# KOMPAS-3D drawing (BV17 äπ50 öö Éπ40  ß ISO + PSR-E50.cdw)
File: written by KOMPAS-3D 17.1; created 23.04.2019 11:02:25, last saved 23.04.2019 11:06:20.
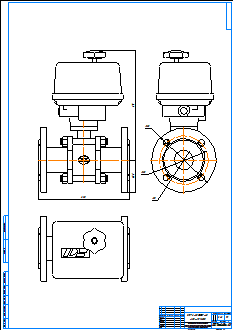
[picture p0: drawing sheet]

Sheet 1: A1, portrait

Title block, sheet 1: name: BV17 Ду50 ФФ Ру40 / с ISO + PSR-E50; material: Внимание! Данный продукт является объектом авторского права ООО «Торговый Дом АДЛ». / Запрещается изменение, копирование, распространение / (в том числе путем копирования на другие сайты и ресурсы в Интернете) / или любое иное использование информации и объектов без предварительного / согласия правообладателя (ООО «Торговый Дом АДЛ»).; mass: 34,3; sheets: 1; organisation: ООО "Торговый дом АДЛ"; sheet format: A1

Views: Вид 1, Проекционный вид 2, Проекционный вид 3
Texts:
  user
Dimensions and other numbers on the sheet: 279; 82,5; 230; 165; 125; 50; 1:1; 1; 34,3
